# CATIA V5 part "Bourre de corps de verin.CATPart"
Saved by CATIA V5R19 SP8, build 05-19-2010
Part number: Bourre
Revision: ANY
Definition: UNKNOWN
Nomenclature: Bourre de corps de verin
Source: Unknown
Bounding box of the stored display mesh (mm): x -6.25 to 6.25, y -6.25 to 6.25, z 0 to 15
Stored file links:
  D:\Documents\1_Travail\1 - ac-limoges.fr\OneDrive - ac-limoges.fr\STI2D_Turgot\2 -2I2D\3_SEQUENCE_Serre_Connectée\3- Spécificités\ITEC\EC 3 Ouverture automatique\Simulation  Ouverture Automatique\Bourre de corps de verin.CATPart
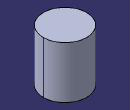
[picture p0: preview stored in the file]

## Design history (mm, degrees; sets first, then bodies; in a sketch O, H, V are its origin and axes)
Body1 "NONE" (main body)
  Solid1: solid without history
